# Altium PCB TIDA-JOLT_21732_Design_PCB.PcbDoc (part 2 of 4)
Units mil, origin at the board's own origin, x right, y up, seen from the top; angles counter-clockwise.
Board outline 5511.81 x 3149.61 mil, 4 copper layers (Top Layer, Power, Ground, Bottom Layer), stack 104.204 mil thick; 440 components, 201 nets, 1044 pads, 391 vias.
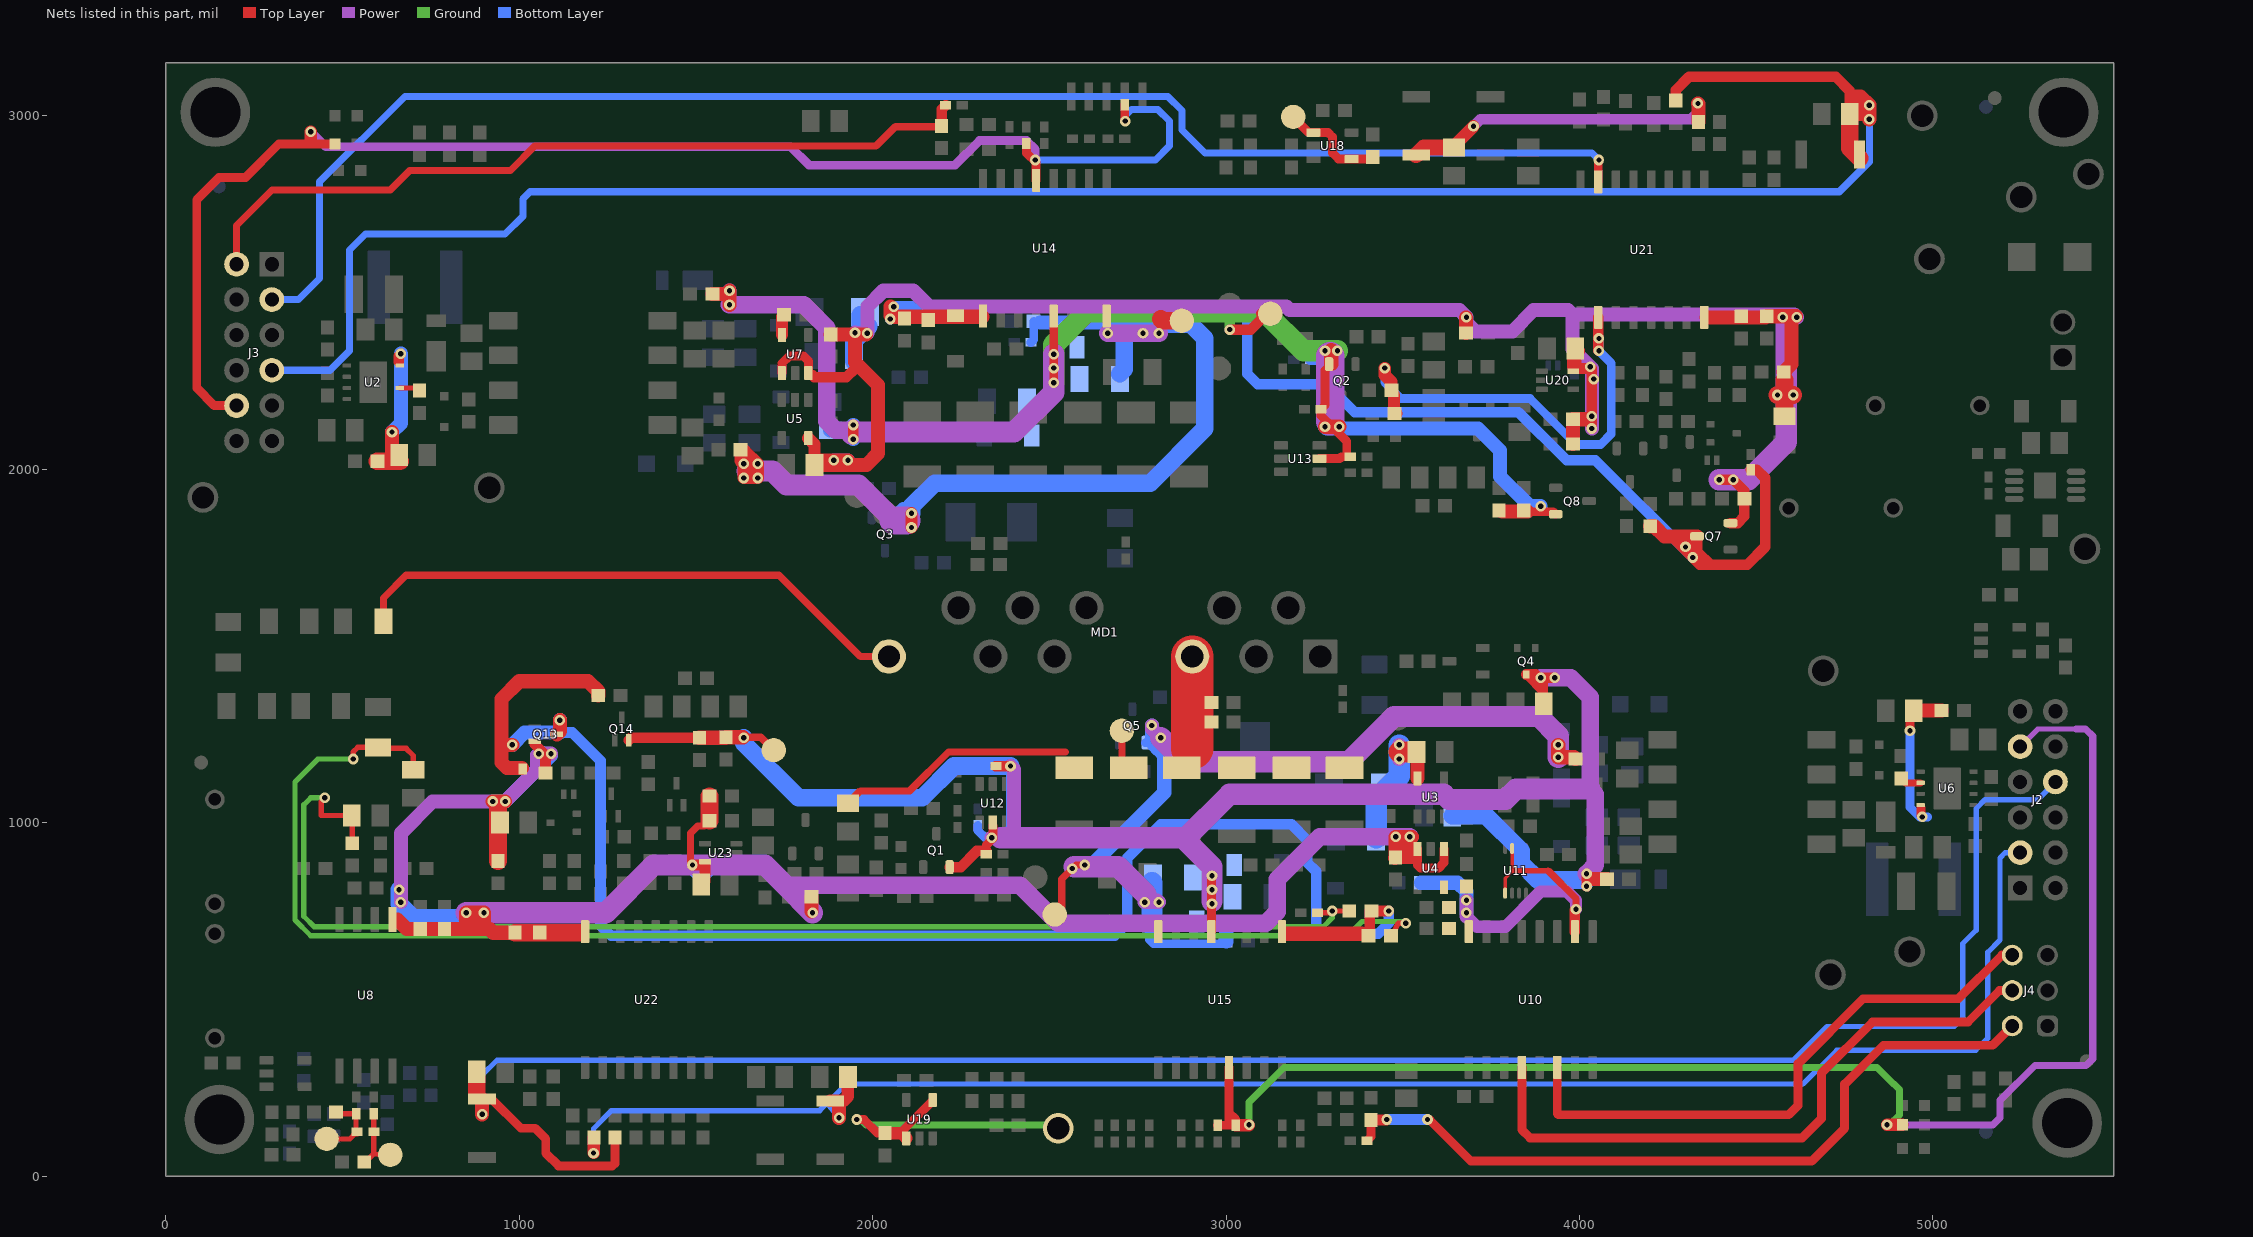
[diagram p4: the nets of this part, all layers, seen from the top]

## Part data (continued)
C3 C25: "CAP, CERM, 0.1 μF, 100 V,+/- 10%, X7R, 0805", Cap_Case=0805, Manufacturer=MuRata, Supplier Part Number 1=490-12005-1-ND, TempCo=X7R, Tolerance_%=10, Value2=100V, ValueDisplayed=0.1μF
C4: library part CMP-0008965-2, "CAP, CERM, 10 uF, 25 V, +/- 10%, X7R, 1206", Cap_Case=2220, Manufacturer=MuRata, Supplier Part Number 1=81-GRM31CR71E106KA12, TempCo=X7R, Tolerance_%=10%, Value1=Unknown, Value2=25V, ValueDisplayed=10uF
C5 C11: library part CMP-0008349-2, "CAP, CERM, 0.1 uF, 50 V, +/- 10%, X7R, 0805", Cap_Case=0805, Manufacturer=MuRata, Supplier Part Number 1=490-1666-1-ND, TempCo=X7R, Tolerance_%=10%, Value1=Unknown, Value2=50V, ValueDisplayed=0.1uF
C6 C26: "CAP, CERM, 220 pF, 100 V,+/- 5%, C0G/NP0, 0603", Cap_Case=0603, Manufacturer=MuRata, Supplier Part Number 1=490-1359-1-ND, TempCo=C0G/NP0, Tolerance_%=5, Value2=100V, ValueDisplayed=220pF
C7 C8 C12 C13 C27 C28 C32 C34: "CAP, CERM, 22 μF, 25 V,+/- 20%, X5R, 0805", Cap_Case=0805, Manufacturer=MuRata, Supplier Part Number 1=490-10749-1-ND, TempCo=X5R, Tolerance_%=20, Value2=25V, ValueDisplayed=22μF
C9 C14 C29 C35: "CAP, CERM, 0.22 μF, 50 V,+/- 10%, X7R, 0805", Cap_Case=0805, Manufacturer=MuRata, Supplier Part Number 1=490-1670-1-ND, TempCo=X7R, Tolerance_%=10, Value2=50V, ValueDisplayed=0.22μF
C10: library part CMP-0008968-2, "CAP, CERM, 2.2 uF, 50 V, +/- 10%, X7R, 1206", Cap_Case=1206, Manufacturer=MuRata, Supplier Part Number 1=490-3367-1-ND, TempCo=X7R, Tolerance_%=10%, Value1=Unknown, Value2=50V, ValueDisplayed=2.2uF
C15 C16 C36 C37: library part CMP-0009609-4, "CAP, CERM, 1500 pF, X1 250 VAC/Y2 300 VAC, +/- 20%, E, TH", Cap_Case=7x5x10mm, Manufacturer=MuRata, Supplier Part Number 1=490-9553-1-ND, TempCo=E, Tolerance_%=20%, Value1=Unknown, ValueDisplayed=1500pF
C17 C38: "CAP, CERM, 0.047 μF, 16 V,+/- 10%, X7R, 0603", Cap_Case=0603, Manufacturer=MuRata, Supplier Part Number 1=490-1529-1-ND, TempCo=X7R, Tolerance_%=10, Value2=16V, ValueDisplayed=0.047μF
C18 C30: library part CMP-0007828-2, "CAP, CERM, 10 uF, 25 V, +/- 10%, X5R, 0805", Cap_Case=0805, Manufacturer=TDK, Supplier Part Number 1=445-5984-1-ND, TempCo=X5R, Tolerance_%=10%, Value1=Unknown, Value2=25V, ValueDisplayed=10uF
C19 C31: library part CMP-0007508-5, "CAP, CERM, 1 uF, 50 V, +/- 10%, X7R, 0603", Cap_Case=0603, Manufacturer="Taiyo Yuden", Supplier Part Number 1=587-3247-1-ND, TempCo=X7R, Tolerance_%=10%, Value1=Unknown, Value2=50V, ValueDisplayed=1uF
C20 C33: library part CMP-0008606-2, "CAP, CERM, 2.2 uF, 16 V, +/- 10%, X7R, 1206", Cap_Case=1206, Manufacturer=Kemet, Supplier Part Number 1=80-C1206C225K4R, TempCo=X7R, Tolerance_%=10%, Value1="0.009 ohm", Value2=16V, ValueDisplayed=2.2uF
C21 C22 C39 C40 C44 C45 C46 C53 C54 C55 C68 C89 C101 C102 C103 C105 C108 C110 C111 C121 C123 C124 C137 C138: "CAP, CERM, 1 μF, 25 V,+/- 10%, X7R, 0603", Cap_Case=0603, Manufacturer=MuRata, Supplier Part Number 1=490-5307-1-ND, TempCo=X7R, Tolerance_%=10, Value2=25V, ValueDisplayed=1μF
C41 C47 C48 C57: "CAP, CERM, 0.01 μF, 50 V,+/- 10%, X7R, 0603", Cap_Case=0603, Manufacturer=MuRata, Supplier Part Number 1=490-1512-1-ND, TempCo=X7R, Tolerance_%=10, Value2=50V, ValueDisplayed=0.01μF
C42 C43 C49 C56 C71 C90 C100 C104 C106 C107 C112 C113 C122 C125 C127: "CAP, CERM, 0.1 μF, 50 V,+/- 10%, X7R, 0603", Cap_Case=0603, Manufacturer=MuRata, Supplier Part Number 1=490-1519-1-ND, TempCo=X7R, Tolerance_%=10, Value2=50V, ValueDisplayed=0.1μF
C50: library part CMP-0006297-2, "CAP, CERM, 0.1 uF, 50 V, +/- 10%, X7R, 0402", Cap_Case=0402, Manufacturer=TDK, PartNumber=C1005X7R1H104K050BB, Supplier Part Number 1=445-5932-1-ND, TempCo=X7R, Tolerance_%=10%, Value1="0.039064 ohm", Value2=50V, ValueDisplayed=0.1uF
C51 C52 C58 C59: "CAP, CERM, 1000 pF, 50 V,+/- 10%, X7R, 0603", Cap_Case=0603, Manufacturer=MuRata, Supplier Part Number 1=490-1494-1-ND, TempCo=X7R, Tolerance_%=10, Value2=50V, ValueDisplayed=1000pF
C60 C61 C62 C63: "CAP, CERM, 100 pF, 100 V,+/- 5%, C0G/NP0, 0603", Cap_Case=0603, Manufacturer=MuRata, Supplier Part Number 1=490-1351-1-ND, TempCo=C0G/NP0, Tolerance_%=5, Value2=100V, ValueDisplayed=100pF
C64 C65: library part CMP-0006562-2, "CAP, CERM, 0.1 uF, 10 V, +/- 10%, X5R, 0402", Cap_Case=0402, Manufacturer=MuRata, PartNumber=GRM155R61A104KA01D, Supplier Part Number 1=490-1318-1-ND, TempCo=X5R, Tolerance_%=10%, Value1=Unknown, Value2=10V, ValueDisplayed=0.1uF
C66 C69 C72 C76: library part CMP-0008584-2, "CAP, CERM, 0.1 uF, 50 V, +/- 5%, X7R, 1206", Cap_Case=1206, Manufacturer=Kemet, Supplier Part Number 1=399-1250-1-ND, TempCo=X7R, Tolerance_%=5%, Value1="0.059 ohm", Value2=50V, ValueDisplayed=0.1uF
C67 C70 C73 C77: library part CMP-0008695-2, "CAP, CERM, 1 uF, 50 V, +/- 10%, X7R, 1206", Cap_Case=1206_180, Manufacturer=TDK, Supplier Part Number 1=445-1423-1-ND, TempCo=X7R, Tolerance_%=10%, Value1="0.009289 ohm", Value2=50V, ValueDisplayed=1uF
C74 C78: library part CMP-0006351-2, "CAP, CERM, 0.1 uF, 16 V, +/- 10%, X7R, 0402", Cap_Case=0402, Manufacturer=MuRata, Supplier Part Number 1=490-4759-2-ND, TempCo=X7R, Tolerance_%=10%, Value1=Unknown, Value2=16V, ValueDisplayed=0.1uF
C75 C79: library part CMP-0006867-4, "CAP, CERM, 1 uF, 25 V, +/- 10%, X7R, 0603", Cap_Case=0603, Manufacturer=Kemet, PartNumber=C0603C105K3RACTU, Supplier Part Number 1=399-7376-1-ND, TempCo=X7R, Tolerance_%=10%, Value1=Unknown, Value2=25V, ValueDisplayed=1uF
C80 C91: library part CMP-0007433-1, "CAP, CERM, 0.01 uF, 50 V, +/- 10%, X7R, 0603", Cap_Case=0603, Manufacturer=MuRata, Supplier Part Number 1=490-1512-1-ND, TempCo=X7R, Tolerance_%=10%, Value1=Unknown, Value2=50V, ValueDisplayed=0.01uF
C81 C82 C83 C84 C85 C92 C93 C94 C95 C96: library part CMP-0006303-2, "CAP, CERM, 100 pF, 50 V, +/- 5%, C0G/NP0, 0402", Cap_Case=0402, Manufacturer="Yageo America", Supplier Part Number 1=311-1024-1-ND, TempCo=C0G/NP0, Tolerance_%=5%, Value1=Unknown, Value2=50V, ValueDisplayed=100pF
C86 C97: library part CMP-0006646-2, "CAP, CERM, 2200 pF, 16 V, +/- 10%, X7R, 0402", Cap_Case=0402, Manufacturer=MuRata, Supplier Part Number 1=GRM155R71C222KA01D-ND, TempCo=X7R, Tolerance_%=10%, Value1=Unknown, Value2=16V, ValueDisplayed=2200pF
C87 C88 C98 C99: library part CMP-0079721-1, "CAP, CERM, 0.01 μF, 25 V,+/- 10%, X7R, 0603", Cap_Case=0603, Manufacturer="Presidio Components", TempCo=X7R, Tolerance_%=10%, Value2=25V, ValueDisplayed=0.01μF
C109 C114 C119 C126 C128 C133: "CAP, CERM, 100 pF, 50 V,+/- 5%, C0G/NP0, 0603", Cap_Case=0603, Manufacturer=MuRata, Supplier Part Number 1=490-1427-1-ND, TempCo=C0G/NP0, Tolerance_%=5, Value2=50V, ValueDisplayed=100pF
C115 C130: "CAP, CERM, 47 pF, 50 V,+/- 5%, C0G/NP0, 0603", Cap_Case=0603, Manufacturer=MuRata, Supplier Part Number 1=490-1419-1-ND, TempCo=C0G/NP0, Tolerance_%=5, Value2=50V, ValueDisplayed=47pF
C116 C129: "CAP, CERM, 0.33 μF, 50 V,+/- 10%, X7R, 0805", Cap_Case=0805, Manufacturer=MuRata, Supplier Part Number 1=490-3327-1-ND, TempCo=X7R, Tolerance_%=10, Value2=50V, ValueDisplayed=0.33μF
C117 C131: "CAP, CERM, 2200 pF, 25 V,+/- 10%, X7R, 0603", Cap_Case=0603, Manufacturer=MuRata, Supplier Part Number 1=GRM188R71E222KA01D-ND, TempCo=X7R, Tolerance_%=10, Value2=25V, ValueDisplayed=2200pF
C118 C120 C132 C134 C135 C136: "CAP, CERM, 470 pF, 50 V,+/- 5%, C0G/NP0, 0603", Cap_Case=0603, Manufacturer=MuRata, Supplier Part Number 1=490-1443-1-ND, TempCo=C0G/NP0, Tolerance_%=5, Value2=50V, ValueDisplayed=470pF
D1: library part CMP-0028407-1, "Diode, Schottky, 60 V, 2 A, SMA", Manufacturer="Diodes Inc.", Supplier Part Number 1=B260A-FDICT-ND, Value1=2A, Value2=0.7V
D2 D11: library part CMP-0005415-2, "Diode, Zener, 24 V, 1 W, PowerDI123", Manufacturer="Diodes Inc.", Power_W=1W, Supplier Part Number 1=DFLZ24DICT-ND
D3 D12: library part CMP-0077072-1, "Diode, Superfast Rectifier, 200 V, 1 A, AEC-Q101, PowerDI123", Manufacturer="Diodes Inc.", Supplier Part Number 1=DFLU1200-7DICT-ND, Value1=1A, Value2=0.98V
D4 D13: library part CMP-0084402-1, "Diode, Zener, 18 V, 500 mW, AEC-Q101, SOD-123", Manufacturer="Diodes Inc.", Power_W=500mW, Value1=0.5W
D5 D14: library part CMP-0029019-1, "Diode, Ultrafast, 75 V, 0.25 A, SOD-323", Manufacturer="Central Semiconductor", Value1=0.25A, Value2=1.2V
D6 D7 D15: library part CMP-0002905-1, "LED, Green, SMD", Color=Green, Manufacturer="Wurth Elektronik", Supplier Part Number 1=732-4971-1-ND, Value1=W, Value2=3.2V
D8 D16: library part CMP-0028782-1, "Diode, Schottky, 100 V, 1 A, AEC-Q101, SOD-123W", Manufacturer=Nexperia, Supplier Part Number 1=568-12693-1-ND, Value1=1A, Value2=0.77V
D9 D18: library part CMP-0005813-1, "Diode, Zener, 8.2 V, 500 mW, SOD-123", Manufacturer="Diodes Inc.", Power_W=500mW, Supplier Part Number 1=BZT52C8V2-FDICT-ND, Value1=0.5W
D10 D17: library part CMP-0005529-3, "Diode, Zener, 5.1 V, 1 W, SMA", Manufacturer="Diodes Inc.", Power_W=1W
D19 D20: "LED, Super Red, SMD", Color="super red", Manufacturer="Wurth Elektronik", Supplier Part Number 1=732-4979-1-ND, Value1=W, Value2=1.9V
D21 D26: library part CMP-0005553-2, "Diode, TVS, Bi, 19 V, SMB", Manufacturer=Littelfuse, Power_W=5W, Supplier Part Number 1=SMBJ20CALFDKR-ND
D22 D23 D24 D27 D28 D29: library part CMP-0002893-1, "LED, Super Red, SMD", Color="super red", Manufacturer="Wurth Elektronik", Supplier Part Number 1=732-4979-1-ND, Value1=W, Value2=1.9V
D25 D30: library part CMP-0077598-3, "Diode, Zener, 4.7 V, 500 mW, SOD-123", Manufacturer=Vishay-Semiconductor, Power_W=500mW, Value1=0.5W
D31 D33 D35 D36 D41 D42: library part CMP-0028877-2, "Diode, Schottky, 30 V, 0.1 A, AEC-Q101, SOD882", Manufacturer=Nexperia, Value1=0.1A, Value2=0.35V
D32 D38: library part CMP-0076957-3, "Diode, Switching, 75 V, 0.3 A, SOD-523", Manufacturer="Micro Commercial Components", Value1=0.3A, Value2=1.25V
FID1 FID2 FID3 FID4 FID5 FID6: library part CMP-0077181-1, "Fiducial mark.  There is nothing to buy or mount.", Manufacturer=N/A
"High Voltage" High_Voltage: library part IEC_HighVoltage, "IEC 61010-1 High Voltage Warning"
J1: library part CMP-0075076-1, "Terminal Block, 2.54mm, 2x1, Brass, TH", Manufacturer="On-Shore Technology", Supplier Part Number 1=ED10561-ND
J2 J3: library part CMP-0075545-2, "Header, 2.54 mm, 6x2, Gold, R/A,TH", Color=Black, Current_A=6.3A, Manufacturer=Samtec, Supplier Part Number 1=SAM1049-06-ND, Voltage_V=550V
J4: library part CMP-0077741-2, "Header, 2.54mm, 3x2, Gold, R/A, TH", Color=Black, Current_A=3A, Manufacturer=Molex, Supplier Part Number 1=WM50030-06-ND, Voltage_V=350V
Logo1: library part CMP-0074839-1
Logo2: library part CMP-0074847-1, "FCC_disclaimer"
MD1: library part CMP-0086469-1, "MOD IGBT MED PWR 14MDIP", Manufacturer="Infineon Technologies"
Q1 Q2: library part "BC857C-7-F, Diodes Inc.", "Transistor, PNP, 45 V, 0.1 A, SOT-23", Manufacturer="Diodes Inc.", Supplier Part Number 1=BC857C-FDICT-ND, Value1="0.1 A", Value2=600
Q3 Q5 Q9 Q17: library part CMP-0000739-1, "MOSFET, N-CH, 40 V, 5.6 A, SOT-23", Alternate Manufacturer=None, Manufacturer=Vishay-Siliconix, Supplier Part Number 1=SI2318CDS-T1-GE3CT-ND, Value1=0.05, Value2="5.8 nC"
Q4: library part CMP-0000406-2, "Transistor, NPN, 40 V, 0.2 A, SOT-323", Manufacturer="Diodes Inc.", Supplier Part Number 1=MMST3904-FDICT-ND, Value1="0.2 A", Value2=400
Q6 Q12: library part CMP-0000759-1, "MOSFET, N-CH, 50 V, 0.3 A, SOT-323", Alternate Manufacturer=None, Manufacturer="Diodes Inc.", Supplier Part Number 1=DMN5L06WKDICT-ND
Q7 Q8: library part CMP-0064870-1, "Transistor, PNP, 60 V, 1 A, AEC-Q101, SOT-23", Manufacturer="Diodes Inc.", Supplier Part Number 1=DPBT8105DICT-ND, Value1="1 A", Value2=300
Q10 Q11: library part CMP-0064871-1, "Transistor, NPN, 60 V, 1 A, AEC-Q101, SOT-23", Manufacturer="Diodes Inc.", Supplier Part Number 1=DNBT8105DICT-ND, Value1="1 A", Value2=300
Q13 Q14: library part CMP-0000362-2, "Transistor, PNP, 60 V, 0.6 A, AEC-Q101, SOT-523", Manufacturer="Diodes Inc.", Supplier Part Number 1=MMBT2907AT-FDICT-ND, Value1="0.6 A", Value2=300
Q15 Q16: library part CMP-0000405-2, "Transistor, NPN, 40 V, 0.2 A, SOT-523", Manufacturer="Diodes Inc.", Supplier Part Number 1=MMBT3904T-FDICT-ND, Value1="0.2 A", Value2=300
R1 R12: "RES, 100, 1%, 0.125 W, 0805", Manufacturer=Vishay-Dale, Power_W=0.125, Supplier Part Number 1=541-100CCT-ND, TempCo="100 ppm/C", Tolerance_%=1, Value1=1%, Value2=0.125W, Value_Code=100R, ValueDisplayed=100
R2 R8 R13 R19 R108 R109: library part CMP-0025874-3, "RES, 0, 5%, 0.1 W, 0603", Manufacturer=Panasonic, Power_W=100mW, Supplier Part Number 1=P0.0GCT-ND, TempCo="600 ppm/C", Tolerance_%=5%, Value2=0.1W, Value_Code=0000, ValueDisplayed=0
R3 R14: "RES, 20.0 k, 1%, 0.125 W, 0805", Manufacturer=Vishay-Dale, Power_W=0.125, Supplier Part Number 1=541-20.0KCCT-ND, TempCo="100 ppm/C", Tolerance_%=1, Value1=1%, Value2=0.125W, Value_Code=20k0, ValueDisplayed=20.0k
R4: "RES, 3.32 k, 1%, 0.063 W, 0402", Manufacturer=Vishay-Dale, Power_W=0.063, Supplier Part Number 1=541-3.32KLCT-ND, TempCo="100 ppm/C", Tolerance_%=1, Value1=1%, Value2=0.063W, Value_Code=3k32, ValueDisplayed=3.32k
R5 R16: "RES, 100 k, 1%, 0.125 W, 0805", Manufacturer=Vishay-Dale, Power_W=0.125, Supplier Part Number 1=541-100KCCT-ND, TempCo="100 ppm/C", Tolerance_%=1, Value1=1%, Value2=0.125W, Value_Code=100k
R6 R17: "RES, 154 k, 1%, 0.1 W, 0603", Manufacturer=Vishay-Dale, Power_W=0.1, Supplier Part Number 1=541-154KHCT-ND, TempCo="100 ppm/C", Tolerance_%=1, Value1=1%, Value2=0.1W, Value_Code=154k
R7 R18: "RES, 301 k, 1%, 0.1 W, 0603", Manufacturer=Vishay-Dale, Power_W=0.1, Supplier Part Number 1=541-301KHCT-ND, TempCo="100 ppm/C", Tolerance_%=1, Value1=1%, Value2=0.1W, Value_Code=301k
R9 R20: "RES, 976 k, 1%, 0.1 W, 0603", Manufacturer=Vishay-Dale, Power_W=0.1, Supplier Part Number 1=541-976KHCT-ND, TempCo="100 ppm/C", Tolerance_%=1, Value1=1%, Value2=0.1W, Value_Code=976k
R10 R15: library part CMP-0020448-2, "RES, 10, 5%, 0.125 W, 0805", Manufacturer=Vishay-Dale, Power_W=125mW, Supplier Part Number 1=541-10ACT-ND, TempCo="200 ppm/C", Tolerance_%=5%, Value2=0.125W, Value_Code=10R0, ValueDisplayed=10
R11 R21: "RES, 12.1 k, 1%, 0.125 W, 0805", Manufacturer=Vishay-Dale, Power_W=0.125, Supplier Part Number 1=541-12.1KCCT-ND, TempCo="100 ppm/C", Tolerance_%=1, Value1=1%, Value2=0.125W, Value_Code=12k1, ValueDisplayed=12.1k
R22 R23 R24 R25 R26 R27: "RES, 221 k, 1%, 0.25 W, 1206", Manufacturer=Vishay-Dale, Power_W=0.25, Supplier Part Number 1=541-221KFCT-ND, TempCo="100 ppm/C", Tolerance_%=1, Value1=1%, Value2=0.25W, Value_Code=221k
R28 R31 R118 R119 R120 R126 R143 R144 R145 R151: "RES, 2.49 k, 1%, 0.125 W, 0805", Manufacturer=Vishay-Dale, Power_W=0.125, Supplier Part Number 1=541-2.49KCCT-ND, TempCo="100 ppm/C", Tolerance_%=1, Value1=1%, Value2=0.125W, Value_Code=2k49, ValueDisplayed=2.49k
R29 R71 R79 R99 R105: "RES, 0, 5%, 0.1 W, 0603", Manufacturer=Vishay-Dale, Power_W=0.1, Supplier Part Number 1=541-0.0GCT-ND, TempCo="200 ppm/C", Tolerance_%=5, Value1=5%, Value2=0.1W, Value_Code=0000, ValueDisplayed=0
R30 R40 R131 R161: "RES, 15.0 k, 1%, 0.1 W, 0603", Manufacturer=Vishay-Dale, Power_W=0.1, Supplier Part Number 1=541-15.0KHCT-ND, TempCo="100 ppm/C", Tolerance_%=1, Value1=1%, Value2=0.1W, Value_Code=15k0, ValueDisplayed=15.0k
R32 R33 R37 R38: "RES, 4.64 k, 1%, 0.1 W, 0603", Manufacturer=Vishay-Dale, Power_W=0.1, Supplier Part Number 1=541-4.64KHCT-ND, TempCo="100 ppm/C", Tolerance_%=1, Value1=1%, Value2=0.1W, Value_Code=4k64, ValueDisplayed=4.64k
R34 R35: "RES, 1.21 k, 1%, 0.1 W, 0603", Manufacturer=Vishay-Dale, Power_W=0.1, Supplier Part Number 1=541-1.21KHCT-ND, TempCo="100 ppm/C", Tolerance_%=1, Value1=1%, Value2=0.1W, Value_Code=1k21, ValueDisplayed=1.21k
R36 R72 R101: "RES, 49.9, 1%, 0.1 W, 0603", Manufacturer=Vishay-Dale, Power_W=0.1, Supplier Part Number 1=541-49.9HCT-ND, TempCo="100 ppm/C", Tolerance_%=1, Value1=1%, Value2=0.1W, Value_Code=49R9, ValueDisplayed=49.9
R39 R42: library part CMP-0025963-2, "RES, 10.0, 1%, 0.063 W, 0402", Manufacturer=Vishay-Dale, Power_W=63mW, Supplier Part Number 1=541-10.0LCT-ND, TempCo="100 ppm/C", Tolerance_%=1%, Value2=0.063W, Value_Code=10R0, ValueDisplayed=10.0
R41 R78 R82: library part CMP-0026822-3, "RES, 0, 5%, 0.063 W, AEC-Q200 Grade 0, 0402", Manufacturer=Vishay-Dale, Power_W=63mW, Supplier Part Number 1=541-0.0JCT-ND, TempCo="200 ppm/C", Tolerance_%=5%, Value2=0.063W, Value_Code=0000, ValueDisplayed=0
R43 R44 R130 R154: "RES, 2.49 k, 1%, 0.1 W, 0603", Manufacturer=Vishay-Dale, Power_W=0.1, Supplier Part Number 1=541-2.49KHCT-ND, TempCo="100 ppm/C", Tolerance_%=1, Value1=1%, Value2=0.1W, Value_Code=2k49, ValueDisplayed=2.49k
R45 R46: library part CMP-0026403-1, "RES, 49.9 k, 1%, 0.063 W, 0402", Manufacturer=Vishay-Dale, Power_W=63mW, Supplier Part Number 1=541-49.9KLCT-ND, TempCo="100 ppm/C", Tolerance_%=1%, Value2=0.063W, Value_Code=49k9, ValueDisplayed=49.9k
R47 R49: "RES, 240 k, 1%, 0.063 W, 0402", Manufacturer=Vishay-Dale, Power_W=0.063, Supplier Part Number 1=541-240KLCT-ND, TempCo="100 ppm/C", Tolerance_%=1, Value1=1%, Value2=0.063W, Value_Code=240k
R48 R50: "RES, 10.0 k, 1%, 0.063 W, 0402", Manufacturer=Vishay-Dale, Power_W=0.063, Supplier Part Number 1=541-10.0KLCT-ND, TempCo="100 ppm/C", Tolerance_%=1, Value1=1%, Value2=0.063W, Value_Code=10k0, ValueDisplayed=10.0k
R51 R54: "RES, 1.82 k, 1%, 0.063 W, 0402", Manufacturer=Vishay-Dale, Power_W=0.063, Supplier Part Number 1=541-1.82KLCT-ND, TempCo="100 ppm/C", Tolerance_%=1, Value1=1%, Value2=0.063W, Value_Code=1k82, ValueDisplayed=1.82k
R52 R53: "RES, 11.0 k, 1%, 0.1 W, 0603", Manufacturer=Vishay-Dale, Power_W=0.1, Supplier Part Number 1=541-11.0KHCT-ND, TempCo="100 ppm/C", Tolerance_%=1, Value1=1%, Value2=0.1W, Value_Code=11k0, ValueDisplayed=11.0k
R55 R170: "RES, 3.32 k, 1%, 0.1 W, 0603", Manufacturer=Vishay-Dale, Power_W=0.1, Supplier Part Number 1=541-3.32KHCT-ND, TempCo="100 ppm/C", Tolerance_%=1, Value1=1%, Value2=0.1W, Value_Code=3k32, ValueDisplayed=3.32k
R56 R57: "RES, 5.76 k, 1%, 0.063 W, 0402", Manufacturer=Vishay-Dale, Power_W=0.063, Supplier Part Number 1=541-5.76KLCT-ND, TempCo="100 ppm/C", Tolerance_%=1, Value1=1%, Value2=0.063W, Value_Code=5k76, ValueDisplayed=5.76k
R58 R83: "RES, 10, 5%, 0.125 W, 0805", Manufacturer=Vishay-Dale, Power_W=0.125, Supplier Part Number 1=541-10ACT-ND, TempCo="200 ppm/C", Tolerance_%=5, Value1=5%, Value2=0.125W, Value_Code=10R0, ValueDisplayed=10
R59 R60 R61 R85 R86 R87: library part CMP-0026754-1, "RES, 10.0 k, 1%, 0.063 W, AEC-Q200 Grade 0, 0402", Manufacturer="Stackpole Electronics Inc", Power_W=63mW, Supplier Part Number 1=RMCF0402FT10K0CT-ND, TempCo="100 ppm/C", Tolerance_%=1%, Value2=0.063W, Value_Code=10k0, ValueDisplayed=10.0k
R62 R64 R88 R90: library part CMP-0025951-2, "RES, 100, 1%, 0.063 W, 0402", Manufacturer=Vishay-Dale, PartNumber=CRCW0402100RFKED, Power_W=63mW, Supplier Part Number 1=541-100LCT-ND, TempCo="100 ppm/C", Tolerance_%=1%, Value2=0.063W, Value_Code=100R, ValueDisplayed=100
R63 R65 R66 R67 R68 R70 R89 R91 R93 R94 R95 R98: "RES, 5.1, 5%, 0.75 W, AEC-Q200 Grade 0, 2010", Manufacturer=Vishay-Dale, Power_W=0.75, Supplier Part Number 1=541-5.1WCT-ND, TempCo="200 ppm/C", Tolerance_%=5, Value1=5%, Value2=0.75W, Value_Code=5R10, ValueDisplayed=5.1
R69 R96 R121 R147: "RES, 10.0 k, 1%, 0.1 W, 0603", Manufacturer=Vishay-Dale, Power_W=0.1, Supplier Part Number 1=541-10.0KHCT-ND, TempCo="100 ppm/C", Tolerance_%=1, Value1=1%, Value2=0.1W, Value_Code=10k0, ValueDisplayed=10.0k
R73 R100: "RES, 10.0, 0.1%, 0.1 W, 0603", Manufacturer=Vishay-Dale, Power_W=0.1, Supplier Part Number 1=TNP10.0AACT-ND, TempCo="25 ppm/C", Value1=0.1%, Value2=0.1W, Value_Code=10R0, ValueDisplayed=10.0
R74 R80 R84 R106: "RES, 2.00, 1%, 0.25 W, 1206", Manufacturer=Vishay-Dale, Power_W=0.25, Supplier Part Number 1=541-2.00FFCT-ND, TempCo="100 ppm/C", Tolerance_%=1, Value1=1%, Value2=0.25W, Value_Code=2R00, ValueDisplayed=2.00
R75 R76 R77 R102 R103 R104: "RES, 3.48 k, 1%, 0.1 W, 0603", Manufacturer=Vishay-Dale, Power_W=0.1, Supplier Part Number 1=541-3.48KHCT-ND, TempCo="100 ppm/C", Tolerance_%=1, Value1=1%, Value2=0.1W, Value_Code=3k48, ValueDisplayed=3.48k
R81 R107 R111 R113 R114 R116 R134 R135 R137 R138 R139 R142 R157 R158 R160 R163 R164 R166: "RES, 10.2 k, 1%, 0.1 W, 0603", Manufacturer=Vishay-Dale, Power_W=0.1, Supplier Part Number 1=541-10.2KHCT-ND, TempCo="100 ppm/C", Tolerance_%=1, Value1=1%, Value2=0.1W, Value_Code=10k2, ValueDisplayed=10.2k
R92 R122 R148: "RES, 10.0 k, 1%, 0.125 W, 0805", Manufacturer=Vishay-Dale, Power_W=0.125, Supplier Part Number 1=541-10.0KCCT-ND, TempCo="100 ppm/C", Tolerance_%=1, Value1=1%, Value2=0.125W, Value_Code=10k0, ValueDisplayed=10.0k
R97: "RES, 2.49 k, 0.1%, 0.125 W, 0805", Manufacturer="Yageo America", Power_W=0.125, Supplier Part Number 1=9982892, TempCo="25 ppm/C", Tolerance_%=0.1, Value1=0.1%, Value2=0.125W, Value_Code=2k49, ValueDisplayed=2.49k
R110 R112 R129 R153: "RES, 1.02 k, 1%, 0.1 W, 0603", Manufacturer=Vishay-Dale, Power_W=0.1, Supplier Part Number 1=541-1.02KHCT-ND, TempCo="100 ppm/C", Tolerance_%=1, Value1=1%, Value2=0.1W, Value_Code=1k02, ValueDisplayed=1.02k
R115 R117: "RES, 100 k, 1%, 0.1 W, 0603", Manufacturer=Vishay-Dale, Power_W=0.1, Supplier Part Number 1=541-100KHCT-ND, TempCo="100 ppm/C", Tolerance_%=1, Value1=1%, Value2=0.1W, Value_Code=100k
R123 R150: "RES, 4.02 k, 1%, 0.125 W, 0805", Manufacturer=Vishay-Dale, Power_W=0.125, Supplier Part Number 1=541-4.02KCCT-ND, TempCo="100 ppm/C", Tolerance_%=1, Value1=1%, Value2=0.125W, Value_Code=4k02, ValueDisplayed=4.02k
R124 R146: "RES, 470, 5%, 0.1 W, 0603", Manufacturer=Vishay-Dale, Power_W=0.1, Supplier Part Number 1=541-470GCT-ND, TempCo="200 ppm/C", Tolerance_%=5, Value1=5%, Value2=0.1W, Value_Code=470R, ValueDisplayed=470
R125 R127 R141 R149 R152 R167: "RES, 4.99 k, 1%, 0.1 W, 0603", Manufacturer=Vishay-Dale, Power_W=0.1, Supplier Part Number 1=541-4.99KHCT-ND, TempCo="100 ppm/C", Tolerance_%=1, Value1=1%, Value2=0.1W, Value_Code=4k99, ValueDisplayed=4.99k
R128 R132 R155 R162: "RES, 3.01 k, 1%, 0.125 W, 0805", Manufacturer=Vishay-Dale, Power_W=0.125, Supplier Part Number 1=541-3.01KCCT-ND, TempCo="100 ppm/C", Tolerance_%=1, Value1=1%, Value2=0.125W, Value_Code=3k01, ValueDisplayed=3.01k
R133 R136 R156 R159 R168 R169: "RES, 100, 1%, 0.1 W, 0603", Manufacturer=Vishay-Dale, Power_W=0.1, Supplier Part Number 1=541-100HCT-ND, TempCo="100 ppm/C", Tolerance_%=1, Value1=1%, Value2=0.1W, Value_Code=100R, ValueDisplayed=100
R140 R165: "RES, 24.9, 1%, 0.125 W, 0805", Manufacturer=Vishay-Dale, Power_W=0.125, Supplier Part Number 1=541-24.9CCT-ND, TempCo="100 ppm/C", Tolerance_%=1, Value1=1%, Value2=0.125W, Value_Code=24R9, ValueDisplayed=24.9
R171: "RES, 9.09 k, 1%, 0.1 W, 0603", Manufacturer=Vishay-Dale, Power_W=0.1, Supplier Part Number 1=541-9.09KHCT-ND, TempCo="100 ppm/C", Tolerance_%=1, Value1=1%, Value2=0.1W, Value_Code=9k09, ValueDisplayed=9.09k
S1 S2 S3 S4 S5 S6: library part CMP-0002113-2, "Switch, Push Button, SMD", CurrentRating_mA=50A, Manufacturer=Alps, Supplier Part Number 1=688-SKRKAE
T1 T?: library part CMP-0087757-1, "Flyback Transformer", Manufacturer=Coilcraft
TP1 TP3 TP18 TP26: library part CMP-0055142-1, "Test Point, Compact, Red, TH", Color=Red, Manufacturer=Keystone, Supplier Part Number 1=36-5005-ND
TP2 TP23 TP24: library part CMP-0055143-1, "Test Point, Compact, Black, TH", Color=Black, Manufacturer=Keystone, Supplier Part Number 1=36-5006-ND
TP4 TP5 TP6 TP7 TP8 TP9 TP10 TP11 TP12 TP17 TP19 TP20 TP21 TP22 TP25: library part CMP-0055027-1, "PCB Pin, 20mil Dia, Gold, TH", Manufacturer=Mill-Max, Supplier Part Number 1=ED90418-ND
TP13 TP14 TP15 TP16: library part CMP-0055155-1, "Test Point, Compact, Blue, TH", Color=Blue, Manufacturer=Keystone, Supplier Part Number 1=36-5122-ND
U1: library part CMP-0013313-4, "300mA High-Voltage Ultra-Low-Iq Low-Dropout (LDO) Regulator, DGN0008D (VSSOP-8)", Alternate Manufacturer="Texas Instruments"
U2 U6: library part CMP-0078633-2, "70-V PSR Flyback Converter With 100-V, 1.2-A Power Switch and Ultra-Low IQ, NGU0008C (WSON-8)", Alternate Manufacturer="Texas Instruments", Alternate PartNumber=LM5180QNGUTQ1
U3 U5: library part CMP-0079136-1, "150-mA, 30-V, Ultra-Low IQ, Wide Input LDO with Reverse Current Protection for Automotive, DBV0005A (SOT-23-5)", Alternate Manufacturer="Texas Instruments"
U4 U7: library part CMP-0073750-1, "Capacitor-Free, 150-mA, LDO Regulator w/ Foldback Current Limit, DBV0005A (SOT-23-5)", Alternate Manufacturer="Texas Instruments"
U8: library part CMP-0013503-2, "Precision, 2-V Input, Reinforced Isolated Amplifier, DWV0008A (SOIC-8)", Alternate Manufacturer="Texas Instruments", Alternate PartNumber=AMC1311DWV, PartNumber=AMC1311QDWVRQ1
U9: library part CMP-0077859-1, "Automotive Qualified Precision, Zero-Crossover, 20MHz, 0.9pA Ib, RRIO, CMOS Operational Amplifier, DBV0005A (SOT-23-5)", Alternate Manufacturer="Texas Instruments", Alternate PartNumber=OPA320AQDBVTQ1
U10: library part CMP-0076066-3, "Automotive, High Speed, Robust EMC Quad-Channel Digital Isolators, DW0016B (SOIC-16)", Alternate Manufacturer="Texas Instruments", Alternate PartNumber=ISO7742FQDWQ1, Operating Temperature Range="-40 to 125 C", Rating=Automotive
U11: library part CMP-0075945-2, "Ultra-Low-Power Ultra-Small-Size 12-Bit 2MSPS SAR ADC, DCU0008A (VSSOP-8)", Alternate Manufacturer="Texas Instruments", Operating Temperature Range="-40 to 125 C", Rating=Automotive
U12 U13: library part CMP-0067337-2, "Automotive, High-Voltage (18V) Window Comparator with Over- and Undervoltage Detection, DDC0006A (SOT-23-T-6)", Alternate Manufacturer="Texas Instruments"
U14 U15: library part CMP-0080538-2, "Single Channel Isolated Gate Driver for SiC/IGBT with Advanced Protection and High-CMTI, DW0016B (SOIC-16)", Alternate Manufacturer="Texas Instruments", Alternate PartNumber=UCC21732QDWRQ1
U16: library part CMP-0033164-1, "Automotive Catalog Adjustable Precision Shunt Regulator, 34 ppm / degC, 100 mA, -40 to 125 degC, 3-pin SOT-23 (DBZ), Green (RoHS & no Sb/Br)", Manufacturer="Texas Instruments", Rating=Automotive, Temp Coeff(Typ)(ppm/ degree C)=34
U17: library part CMP-0051573-1, "Automotive Catalog Single 2-Input Positive-AND Gate, DBV0005A, LARGE T&R", F @ Nom Voltage(Max)(Mhz)=75, Generic Part Number=SN74AHC1G08-Q1, ICC @ Nom Voltage(Max)(mA)=0.01, Manufacturer="Texas Instruments", Operating Temperature Range(C)="-40 to 125", Rating=Automotive, tpd @ Nom Voltage(Max)(ns)=12.3,7.9, Voltage(Nom)(V)=3.3,5
U18 U19: library part CMP-0042686-1, "Automotive Catalog 550 uA/Ch, 3 MHz, Rail-to-Rail Output Operational Amplifier, 2.7 to 16 V, -40 to 125 degC, 5-pin SOT23 (DBV5), Green (RoHS & no Sb/Br)", Manufacturer="Texas Instruments", Rating=Automotive, Total Supply Voltage(Max)(+5V is 5, +/-5V is 10)=16, Total Supply Voltage(Min)(+5V is 5, +/-5V is 10)=2.7
U20 U23: library part CMP-0073518-3, "40ns, micro-Power, Rail-to-Rail Input, Single-Channel Comparator with Push-Pull Outputs, DCK0005A (SOT-SC70-5)", Alternate Manufacturer="Texas Instruments", Alternate PartNumber=TLV3201AIDCKT
U21 U22: library part CMP-0860136-1, "Automotive, High Speed, Robust EMC Six-Channel Digital Isolators, DW0016B (SOIC-16)", Alternate Manufacturer="Texas Instruments", Alternate PartNumber=ISO7762FQDWRQ1, Operating Temperature Range="-40 to 125 C", Rating=Automotive
ZZ1: library part CMP-0003616-3
ZZ2: library part CMP-0077236-1
ZZ3: library part CMP-0077237-1
ZZ4: library part CMP-0077238-1

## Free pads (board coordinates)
  round 196.85 hole 141.73: 1(140,3010) 1(151.46,160) 1(5370,3010) 1(5380,150)

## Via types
v1: diameter 30, hole 15, Top Layer to Bottom Layer, 378 vias
v2: diameter 19.68, hole 7.87, Top Layer to Bottom Layer, 13 vias

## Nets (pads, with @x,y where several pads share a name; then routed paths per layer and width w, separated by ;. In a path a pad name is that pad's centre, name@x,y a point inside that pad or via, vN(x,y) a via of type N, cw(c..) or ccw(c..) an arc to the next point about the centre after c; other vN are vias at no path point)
0VInj_AIN_L: J2.3 R151.1 R169.1 S6.2 | length 4951.1
  Top Layer w35: v1@1211.17,66.17 R169.1@1211.17,108.5 ; S6.2@1880,212.68 1917.68,212.68 1930,225 R151.1@1930,280
  Top Layer w40: v1(1905,165) S6.2@1905,210
  Bottom Layer w15: v1(1210,65) 1210,133.83 1261.17,185 1850,185 1925.2,260.2 4632.2,260.2 4727.95,355.95 5120.95,355.95 5155,390 5155,633 5189.8,667.8 5189.8,900 5204.76,914.96 J2.3@5246.77,914.96 ; 1875,200 v1(1905,165)
0VInj_AIN_U: R126.1 R168.1 S3.2 | length 928.2
  Top Layer w35: R126.1@3645,2910 3645,2915 v1(3700,2970)
  Top Layer w40: v1(4335,3035) 4336.75,3033.25 R168.1@4336.75,2982.8
  Top Layer w45: S3.2@3537.91,2888.62 3559.29,2910 R126.1@3645,2910
  Power w30: v1(3700,2970) 3720,2990 4315,2990 4335,3010 v1(4335,3035)
5VInj_AIN_L: J2.8 R145.1 R156.1 S5.2 | length 5891.8
  Top Layer w25: S5.2@895,217.68 922.32,217.68 1005,135 1045,135 1075,105 1075,65 1111.42,28.58 1188.77,28.58 1189.06,28.29 1263.29,28.29 1270.87,35.87 R156.1@1270.87,108.5
  Top Layer w40: v1(895,175) S5.2@895,217.68
  Top Layer w50: S5.2@880,230 R145.1@880,295
  Bottom Layer w15: v1(895,175) 895,285.59 936.96,327.55 4604.3,327.55 4700.05,423.31 5060,423.31 5084.3,447.6 5084.3,657.55 5122.45,695.7 5122.45,1040 5147.45,1065 5296.81,1065 J2.8@5346.77,1114.96
5VInj_AIN_U: J3.7 R120.1 R133.1 S2.2 | length 6023.2
  Top Layer w30: R133.1@4272.04,3042.8 4272.04,3072.04 4310,3110 4725,3110 4765,3070 R120.1@4765,3005
  Top Layer w40: 4795,3005 4795,3040 4780,3055 4795,3055 v1(4820,3030) v1(4820,2990)
  Top Layer w50: R120.1@4765,3005 4765,2907.68 S2.2@4792.68,2880
  Bottom Layer w20: J3.7@300,2280 465,2280 520,2335 520,2620 565,2665 960,2665 1010,2715 1010,2765 1030,2785 4735,2785 4820,2870 v1(4820,2990) v1(4820,3030)
15V_Fault_U: R53.2 R170.2 U21.10 | length 1271.7
  Top Layer w25: v1@4052.91,2337.09 v1(4055,2335)
  Top Layer w30: v1@4052.91,2337.09 U21.10@4052.91,2429.37
  Top Layer w35: v1(3448.7,2286.09) 3448.7,2266.31 3468.03,2246.98 R53.2@3468.03,2223.59 ; R53.2@3475,2210 3475,2164.25 R170.2@3481.5,2157.76
  Bottom Layer w25: v1(3448.7,2286.09) 3448.7,2246.3 3495,2200 3860,2200 3990,2070 4060,2070 4090,2100 4090,2300 v1(4055,2335) v1(4055,2370)
15V_Monitor_L: J4.6 U10.6 | length 1675.4
  Top Layer w25: U10.6@3937.05,307.44 3937.05,176.57 3940,173.62 4592.13,173.62 4618.5,200 4618.5,317.98 4802.02,501.5 5072.02,501.5 5195.49,624.96 J4.6@5224.33,624.96
15V_Monitor_U: J3.3 U21.7 | length 4322.8
  Top Layer w25: U21.7@4052.91,2813.23 4052.91,2872.91 v1(4055,2875)
  Bottom Layer w20: J3.3@300,2480 375,2480 435,2540 435,2813.5 676.5,3055 2835,3055 2875,3015 2875,2960 2940,2895 4035,2895 v1(4055,2875)
+3.3V_L: C22.1 C53.2 C54.1 C56.2 U4.5 U10.10 U10.16 U11.1 U11.7 | length 1076.7
  Top Layer w10: U11.1@3789.45,800.63 3789.45,843.07 3809.13,862.76 U11.7@3809.13,926.61
  Top Layer w15: 3814.13,862.76 3815,863.62 3911.38,863.62
  Top Layer w20: 3911.38,863.62 3990,785 v1(3990,755)
  Top Layer w30: U10.10@3987.05,691.3 v1@3987.05,752.05
  Power w35: v1@3680,735 3710,705 3790,705 3890,805 3965,805 3990,780 v1(3990,755)
  Power w40: v1@3680,735 v1(3680,745) v1(3680,780)
  Bottom Layer w40: C54.1@3551.5,830 3655,830 3680,805 v1(3680,780) v1(3680,745)
+3.3V_U: C40.1 U7.5 | length 59.6
  Top Layer w25: C40.1@1743.3,2431.23 C40.1@1749.2,2437.14
  Top Layer w35: U7.5@1743.3,2380.01 C40.1@1743.3,2431.23
+5V_L: C18.2 C20.1 C21.1 C42.1 C45.2 C122.2 C123.1 C124.2 C126.1 C127.2 D10.1 D41.1 Q13.2 R144.2 R147.2 R149.2 R150.2 U3.5 U4.1 U4.3 U8.1 U22.16 U23.5 | length 6707.6
  Top Layer w20: v1(1490,880) 1485,885 1485,970 1505,990 1523.5,990 C126.1@1538.5,1005
  Top Layer w25: C21.1@3477.48,900 3482.48,895 3541.57,895 ; U4.3@3541.57,925.39 3541.57,895 ; U4.1@3616.38,925.39 3616.38,886.38 3601.26,871.26 3550,871.26 3541.57,879.68 3541.57,895
  Top Layer w30: 1043.5,1221.5 1074.17,1190.83 R149.2@1074.17,1140 ; v1(1490,880) 1516.3,880 ; R150.2@1525.71,834.29 1525.71,880
  Top Layer w40: 655,725 681.5,698.5 C45.2@720.04,698.5 C42.1@788.74,698.5 850,698.5 ; 883.5,720 850,720 ; 900,703.5 v1(900,745) v1(850,745) 850,720 ; v1(925,1060) v1(960,1060) ; C124.2@988.11,688.5 926.5,688.5 916.5,698.5 850,698.5 ; v1@1826.5,748.5 R147.2@1826.5,790 ; C21.1@3477.48,900 C21.1@3478.98,901.5 ; v1@3526.46,958.98 3478.98,958.98 C21.1@3478.98,901.5 ; U4.3@3530,925.39 3502.87,925.39 C21.1@3478.98,901.5 ; C18.2@3538.98,1200 3541.57,1197.4 U3.5@3541.57,1125.39 ; 850,698.5 850,720
  Top Layer w50: C123.1@940,891.5 R144.2@940,994.33 ; 940,1045 R144.2@940,994.33 ; R144.2@945.67,1000 R144.2@940,994.33 ; C124.2@988.11,688.5 C127.2@1058.11,688.5 1172,688.5 ; C126.1@1538.5,1005 C122.2@1538.5,1075
  Top Layer w60: 3490,1200 C18.2@3530,1200
  Power w40: v1(665,775) 665,970 755,1060 v1(925,1060) v1(960,1060) 1050,1150 1050,1190 v1(1055,1195) v1(1090,1195) ; v1(3490,1180) v1(3490,1220)
  Power w50: 1751.77,823.23 2416.77,823.23 2525,715 3112.64,715 3145,747.36 3145,840 3265,960 v1(3480,960) v1(3520,960)
  Power w60: v1(850,745) v1(900,745) 1245,745 1380,880 v1(1490,880) 1695,880 1751.77,823.23 v1(1830,745)
  Bottom Layer w30: v1(1490,880) 1490,865 1496.97,858.03 D41.1@1535,858.03
  Bottom Layer w40: v1(925,1060) v1(960,1060) 1090,1190 1085,1195 v1(1055,1195) 1050,1190 1050,1155.35 ; C20.1@3430,951.91 C20.1@3424.65,957.27 v1@3477.27,957.27
  Bottom Layer w50: v1(660,810) 660,770 700,730 835,730 v1(850,745) v1(900,745)
  Bottom Layer w60: C20.1@3424.65,957.27 3424.65,1065.91 3490,1131.26 v1(3490,1180) v1(3490,1220)
+5V_U: C30.2 C33.1 C39.1 C107.2 C109.1 C110.1 C111.2 C113.2 D17.1 D35.1 Q7.2 R119.2 R121.2 R123.2 R125.2 U5.5 U7.1 U7.3 U20.5 U21.16 | length 6601.3
  Top Layer w25: U7.1@1743.3,2271.75 1743.3,2299.33 1763.96,2320 1805,2320 1818.1,2306.9 U7.3@1818.1,2271.75
  Top Layer w30: 1830,2265 1835,2260 1925.69,2260 1950,2284.31 1950,2302.93 ; v1@1950,2381.5 v1(1950,2386.1) ; 3990,2285 4035,2285 v1(4035,2150) v1(4035,2115) ; v1@4023.7,2141.3 v1@4032.4,2150 ; v1(4395,1970) v1(4435,1970) 4466.5,1938.5 R125.2@4466.5,1916.3 4466.5,1866.5 4447.4,1847.4 Q7.2@4427.24,1847.4
  Top Layer w35: U5.5@1817.68,2088.01 1835.28,2070.41 C30.2@1835.28,2012.14
  Top Layer w40: C39.1@1881.3,2381.5 v1@1950,2381.5 ; v1(1930,2025) v1(1890,2025) 1848.14,2025 C30.2@1835.28,2012.14 1982.14,2012.14 2015,2045 2015,2237.93 1950,2302.93 v1@1950,2381.5 ; v1@1981.5,2381.5 v1@1950,2381.5 ; R121.2@3678.5,2385 v1@3678.5,2428.5 ; C107.2@3981.5,2071.3 C109.1@3981.5,2141.3 v1@4023.7,2141.3 ; 3985,2290 R123.2@3985,2334.21 ; R123.2@3987.91,2341.3 R123.2@3995,2334.21 ; U21.16@4360,2430 4457.9,2429.63 C111.2@4526.38,2429.37 ; C111.2@4529.8,2432.8 v1@4612.2,2432.8 ; C110.1@4577.8,2275.29 4600,2297.49 4600,2420.59
  Top Layer w50: v1(4560,2210) 4580,2210 ; R119.2@4580,2150 4580,2210 ; 4580,2253.5 4580,2210 ; v1(4605,2210) 4580,2210
  Power w40: v1(1890,2025) v1(1930,2025) ; v1(1950,2386.1) v1(1985,2385) 1985,2460 2030,2505 2115,2505 2160.1,2459.9 3170.1,2459.9 3180,2450 3660,2450 v1(3680,2430) 3680,2415 3705,2390 3810,2390 3870,2450 3967.45,2450 3980,2437.45 ; v1(4035,2115) v1(4035,2150) 4035,2285 v1(4030,2290) 3980,2340 3980,2437.45 ; v1(4560,2210) 4585,2210 v1(4605,2210) ; v1(4575,2430) v1(4615,2430) 4607.55,2437.45 3980,2437.45
  Power w60: v1(4395,1970) v1(4435,1970) 4478.31,1970 4585,2076.69 4585,2210 v1@4585,2420
  Bottom Layer w20: D35.1@3986.22,2290 v1(4030,2290)
  Bottom Layer w30: v1(4035,2115) v1(4035,2150) v1@4035,2285
  Bottom Layer w50: C33.1@1946.83,2305.57 C33.1@1946.83,2320.57 1946.83,2361.83 1988.74,2403.74 ; 1965,2400 D17.1@1965,2436.26
  other v1: 4040,2255
+15V_Iso_L: C64.1 C66.1 C67.1 C72.1 C73.1 C138.1 Q1.2 Q4.3 Q14.2 R10.2 R13.2 R45.1 R47.2 R92.2 R152.2 TP6.1 U12.5 U15.5 | length 5687.3
  Top Layer w20: v1@1633.5,1241.5 1683.5,1241.5 TP6.1@1720,1205
  Top Layer w25: R45.1@2321.38,920 2321.38,936.38 2340,955 U12.5@2340,990.87 ; U15.5@2958.31,691.3 v1@2958.31,848.31 ; Q4.3@3848.98,1419.17 3898.98,1369.17 ; v1(3890,1410) 3898.98,1401.02 3898.98,1369.17 ; R92.2@3898.98,1336.58 3898.98,1369.17
  Top Layer w30: Q14.2@1309.69,1233.5 1316.22,1240.04 R152.2@1510,1240.04 ; C138.1@1583.54,1240.04 C138.1@1585,1241.5 ; Q1.2@2217.64,874.02 2249.02,874.02 2295,920 R45.1@2321.38,920 ; R47.2@2348.62,1160 v1(2390,1160) ; Q4.3@3848.98,1419.17 3875,1419.17 3884.17,1410 v1(3890,1410) v1(3930,1410) ; v1(4020,820) v1(4020,855)
  Top Layer w40: R152.2@1510,1240.04 C138.1@1583.54,1240.04 ; C138.1@1585,1241.5 v1@1633.5,1241.5 ; 4025,840 R13.2@4077.48,840
  Power w30: v1(4020,820) v1(4020,855)
  Power w40: v1(2337.01,957.01) 2362.01,957.01 ; v1(2390,1160) 2400.04,1149.96 2400.04,995.04 2400,965
  Power w50: v1(3890,1410) v1(3930,1410) 3975,1410 4030,1355 4030,1095 4045,1080 4045,880 v1(4020,855)
  Power w60: 2362.01,957.01 2877.99,957.01 ; v1@2960,777.45 v1(2960,810) v1(2960,850) 2960,875 2877.99,957.01 ; 4030,1095 3820,1095 3790,1065 3630.75,1065 3615.75,1080 3010,1080 2887.01,957.01 2877.99,957.01
  Bottom Layer w25: C64.1@2297.32,991.38 2297.32,977.68 2317.99,957.01 v1(2337.01,957.01) 2362.05,957.01 2390,984.96 v1(2390,1160)
  Bottom Layer w50: v1(1635,1240) 1635,1225 1790,1070 2140,1070 2230,1160 v1(2390,1160) ; R10.2@3640,1019.64 3735.36,1019.64 3835,920 3835,885 3882.5,837.5 4020,837.5
  other v1: 2960,770
+15V_Iso_U: C65.1 C69.1 C70.1 C76.1 C77.1 C137.1 Q2.2 Q8.2 R2.2 R15.2 R46.1 R49.2 R127.2 TP7.1 U13.5 U14.5 | length 4658.1
  Top Layer w25: v1(2512.18,2245) v1(2512.18,2286.09) v1(2512.18,2325) U14.5@2512.18,2433.43 ; U13.5@3264.13,2030 3321.38,2030 3326.38,2035 3341.38,2035 3341.38,2078.62 3300,2120 3268.62,2151.38 R46.1@3268.62,2170 3280,2181.38 3280,2279.65 Q2.2@3297.6,2297.24 ; R127.2@3852.52,1879.8 3925.55,1879.8 Q8.2@3932.76,1872.6
  Top Layer w30: v1(1945,2085) v1(1945,2125) ; v1(3010,2395) 3070,2395 TP7.1@3115,2440 ; TP7.1@3100,2440 TP7.1@3115,2440 ; TP7.1@3125,2440 TP7.1@3115,2440
  Top Layer w40: R2.2@1546.5,2495.5 1585.5,2495.5 v1(1595,2505) v1(1595,2465) ; v1(3280,2120) 3300,2120 v1(3320,2120) ; Q2.2@3297.6,2297.24 3297.6,2337.4 ; C137.1@3782.52,1879.8 R127.2@3852.52,1879.8
  Power w40: v1(1595,2465) v1(1595,2505)
  Power w50: v1(1595,2465) 1805,2465 1870,2400 1870,2135.9 1895.9,2110 1945,2110
  Power w60: 1940,2100 1945,2105 1945,2110 1950,2105 2400,2105 2512.18,2217.18 v1(2512.18,2245) v1(2512.18,2286.09) v1(2512.18,2325)
  Power w80: 3295,2135 3295,2320
  Ground w30: v1(3010,2395) 3010,2445
  Ground w60: v1(2512.18,2245) v1(2512.18,2286.09) v1(2512.18,2325) 2512.18,2352.18 2605,2445 3010,2445 3108.7,2445 3218.7,2335 v1(3280,2335) v1(3315,2335)
  Bottom Layer w30: C65.1@3238.62,2309.21 3264.21,2309.21 3280,2325 v1(3280,2335)
  Bottom Layer w40: R15.2@1880,2110 1930,2110 v1(1945,2125) v1(1945,2085) ; v1(3280,2120) 3285,2115 3712.89,2115 3775,2052.89 3775,1979.72 3859.72,1895 v1(3890,1895)
-8V_Iso_L: C72.2 C73.2 C74.2 C75.2 Q5.2 R19.2 TP8.1 U15.8 | length 2948.4
  Top Layer w20: TP8.1@2515,740 2535,760 2535,840 v1(2565,870) 2575,880 v1(2600,880)
  Top Layer w40: v1(3940,1220) v1(3940,1185) 3983.94,1185 R19.2@3988.94,1180
  Power w40: v1(2565,870) v1@2570,875 ; v1(2770,775) v1(2810,775) v1@2805,780 ; v1(2790,1275) 2790,1265 v1(2815,1240)
  Power w60: v1@2570,875 2695,875 2772.64,797.36 ; v1(2815,1240) 2882.52,1172.48 3347.48,1172.48 3475,1300 3885,1300 3940,1245 v1(3940,1220) v1(3940,1185)
  Bottom Layer w25: Q5.2@2772.4,1226.18 2791.18,1226.18 ; C73.2@2783.07,720 2782.91,719.84 2782.91,669.28 2794.87,657.32 C75.2@3000.3,657.32
  Bottom Layer w40: v1(2565,870) 2575,880 v1(2600,880) 2620,880 2825,1085 2825,1190 2810,1205 ; 2790,1227.36 v1(2790,1275) ; 2791.18,1226.18 2794.83,1222.08 2810,1205 ; v1@2810,1234.97 2810,1205 ; C75.2@3000.3,664 3000.3,709.45 C74.2@3008.17,717.32
  Bottom Layer w60: C73.2@2790,710 C72.2@2790,830
-8V_Iso_U: C76.2 C77.2 C78.2 C79.2 Q3.2 R8.2 TP9.1 U14.8 | length 3073.4
  Top Layer w35: R8.2@1626.5,2055 1626.5,2023.5 v1(1635,2015) 1635,1995 ; R8.2@1634.43,2052.07 1637.93,2052.07 v1(1675,2015) 1675,1995 ; v1(2110,1835) v1(2110,1875) ; 1635,1995 1675,1995 ; 1635,1995 v1(1635,1975) v1(1675,1975) 1675,1995
  Top Layer w50: 2815,2425 2820,2420 TP9.1@2875,2420
  Power w50: v1(2665,2385) v1(2765,2385) v1(2810,2385)
  Power w60: 1645,1995 1716.28,1995 1756.28,1955 1960,1955 2060,1855
  Power w80: 2060,1855 2095,1855
  Bottom Layer w25: 2090,1855 v1(2110,1835) v1(2110,1875) 2098.82,1863.82 Q3.2@2072.4,1863.82 2075,1866.42 2075,1885 2085,1895 2110,1895 ; C78.2@2447.72,2358.7 2455.59,2366.57 C79.2@2455.59,2418.7 ; C77.2@2711.93,2365 2711.93,2393.07
  Bottom Layer w40: C79.2@2474.29,2415 2715,2415 ; 2720,2410 2715,2415 ; 2730,2415 2715,2415
  Bottom Layer w50: v1(2110,1875) 2110,1895 2175.41,1960.41 2785.41,1960.41 2940,2115 2940,2370 2900,2410 2720,2410 ; C76.2@2699.57,2270 2711.93,2282.36 C77.2@2711.93,2345 C77.2@2711.93,2365
AIN_L: C98.1 D30.1 D38.2 Q13.3 R101.2 R158.2 U15.1 | length 4549.2
  Top Layer w30: R101.2@3403.5,680 3406.5,682.99 C98.1@3406.5,750 ; C98.1@3411.5,750 v1(3460,750)
  Top Layer w40: v1(980,1220) 950,1220 ; D38.2@1006.97,1155 965,1155 950,1170 950,1220 ; Q13.3@1106.5,1250 1115,1258.5 v1(1115,1290) ; R158.2@1223.5,1360 1223.5,1371.5 1195,1400 1000,1400 950,1350 950,1220 ; U15.1@3170,685.53 3382.97,685.53
  Bottom Layer w30: 1115,1255 1150,1255 1230,1175 1230,1125 1230,710 1260,680 2685,680 2720,715 2720,900 2815,995 3185,995 3230,950 3230,886.65 3255,861.65 3255,706.48 3275.94,685.53 D30.1@3308.98,685.53 3430.53,685.53 3460,715 v1(3460,750)
  Bottom Layer w40: v1(980,1220) 1015,1255 1115,1255 v1(1115,1290)
AIN_U: C87.1 D25.1 D32.2 Q7.3 R72.2 R135.2 U14.1 | length 3797.1
  Top Layer w30: 4265,1805 v1(4320,1750) 4340,1730 4371.1,1730 ; v1@4310,1790 4311.59,1788.44 4335.09,1765.36 4371.1,1730 ; 4332.76,1768.35 Q7.3@4332.76,1810 ; D32.2@4485,1998.35 4501.65,1998.35 4525,1975 4525,1780 4475,1730 4371.1,1730
  Top Layer w40: v1@2050,2460 2050,2435 2053.5,2431.5 U14.1@2310.25,2431.5 ; R135.2@4200,1838.5 4211.5,1838.5 4240,1810 Q7.3@4332.76,1810
  Bottom Layer w30: v1(2050,2425) 2050,2450 v1(2060,2460) 2061.15,2461.15 3018.85,2461.15 3060,2420 3060,2270 3090,2240 3285,2240 3363.7,2161.3 3827.2,2161.3 3963.5,2025 4045,2025 v1(4320,1750)
  other v1: 4300,1780
Analog_out_L: R116.2 TP26.1 U19.1 U19.4 | length 887.1
  Top Layer w25: v1(1955,160) 1975,160 2013.9,121.1 R116.2@2048.9,121.1 ; 2080.27,121.5 2080.27,123.51 2169.8,213.04 U19.4@2169.8,215.04
  Top Layer w35: R116.2@2035,121.5 2080.27,121.5 U19.1@2095,106.77
  Ground w20: v1(1955,160) 1966.08,160 1981.08,145 2515,145 TP26.1@2525,135
Analog_out_U: R114.2 TP25.1 U18.1 U18.4 | length 290.7
  Top Layer w25: TP25.1@3190,2996.72 3234.32,2952.4 U18.1@3246.97,2952.4 3288.54,2952.4 3301.1,2939.84 3301.1,2894.84 3318.34,2877.6 U18.4@3355.23,2877.6 R114.2@3405.04,2877.6
APWM_L: C97.1 J4.2 R99.1 | length 2149.6
  Top Layer w25: C97.1@3398.62,100 3410,111.38 R99.1@3410,158.5 ; v1@3576.5,158.5 3692.87,42.13 3811.38,42.13 4657.13,42.13 4750,135 4750,260 4860,370 5169.37,370 J4.2@5224.33,424.96
  Top Layer w30: R99.1@3410,158.5 v1@3453.5,158.5
  Bottom Layer w30: v1(3455,160) v1(3570,160)
APWM_U: C86.1 J3.2 R71.1 | length 2289.3
  Top Layer w20: J3.2@200,2580 200,2690 300,2790 635,2790 690,2845 975,2845 1045,2915 2010,2915 2064.03,2969.03 R71.1@2195,2969.03
  Top Layer w30: R71.1@2197.18,2966.85 2195,2969.03 2195,3018.62 C86.1@2206.38,3030
BUS_N: C50.2 R32.1 R42.1 TP5.1 | length 206.8
  Top Layer w15: TP5.1@455,105 520.31,105 C50.2@538.35,123.03 ; R32.1@482.01,181.3 486.93,176.38 R42.1@538.35,176.38 C50.2@538.35,123.03 ; C50.2@541.38,120 C50.2@538.35,123.03
BUS_P: C50.1 R37.1 R39.1 TP4.1 | length 190.7
  Top Layer w15: R37.1@561.5,40 564.98,40 588.62,63.64 ; R39.1@591.85,176.38 R39.1@588.35,176.38 588.35,120.28 588.62,120 588.62,93.62 588.62,63.64 ; TP4.1@625,55 588.62,63.64
BUSIN_N: C98.2 R31.1 R34.2 R41.2 | length 3662.1
  Top Layer w15: v1(450,1070) 440,1060 440,1020 R31.1@526.38,1020 527.68,1018.7 R34.2@527.68,931.5 ; R41.2@3253.62,745 3295,745 v1(3300,750) C98.2@3348.5,750
  Ground w15: v1(450,1070) 410,1070 390.36,1050.36 390.36,735 420.36,705 3275,705 3300,730 v1(3300,750)
BUSIN_P: R22.1 R28.2 R101.1 | length 4075.2
  Top Layer w15: v1(530,1180) 530,1200 542.91,1212.91 R22.1@600,1212.91 602.91,1210 680,1210 700,1190 R28.2@700,1150 ; R101.1@3466.5,680 3475,690 3486.5,715 v1(3507.96,715)
  Ground w15: 370,720 365.36,724.64 ; v1(530,1180) 430,1180 365.36,1114.64 365.36,724.64 ; v1(3507.96,715) 3502.96,720 3385,720 3345,680 410,680 365.36,724.64
CS_temp_L: J4.4 U10.4 | length 1821.4
  Top Layer w25: U10.4@3837.05,307.44 3837.05,130.83 3860,107.87 4629.89,107.87 4684.25,162.23 4684.25,290.74 4829.26,435.75 5099.26,435.75 5188.47,524.96 J4.4@5224.33,524.96
DU: MD1.14 R27.2 | length 1617.8
  Top Layer w20: R27.2@615.83,1570 615.83,1635.83 680,1700 1735,1700 1965,1470 MD1.14@2045.91,1470
EN_L: R16.1 R20.2 U6.4 | length 424.1
  Top Layer w25: v1(4935,1260) R16.1@4935,1305.75 ; v1@4966.3,1019.84 4966.3,1042
  Top Layer w40: R16.1@4946.1,1316.85 R20.2@5024.61,1316.85
  Bottom Layer w25: v1(4935,1260) 4935,1043.78 4962.64,1016.14 4985,1016.14
  other v1: 4970,1016.14
EN_U: R5.1 R9.2 U2.4 | length 410.6
  Top Layer w30: 658.82,2303.82 658.82,2320.29 v1(665,2326.47)
  Top Layer w40: 622.61,2022.61 640,2040 v1(640,2105)
  Top Layer w50: R9.2@598.59,2022.61 R5.1@662.61,2022.61
  Bottom Layer w40: v1(640,2105) 665,2130 v1(665,2326.47)
FB_L: R17.1 U6.2 | length 60.5
  Top Layer w20: R17.1@4910.13,1125.35 4922.88,1112.59 U6.2@4965.32,1112.59
FB_U: R6.1 U2.2 | length 53.7
  Top Layer w15: U2.2@661.9,2230.01 713.52,2230.01 R6.1@715,2231.5
FLT_L: C95.1 D28.1 J2.9 R86.1 U15.13 | length 4263
  Top Layer w25: C95.1@2976.06,143.62 R86.1@3027.38,143.62 3027.38,160.62 3008.31,179.69 ; 3008.31,145.05 3008.31,179.69 ; U15.13@3008.31,307.44 3008.31,179.69
  Top Layer w35: R86.1@3027.38,143.62 v1@3063.62,143.62 ; v1(4870,145) D28.1@4913.5,145
  Power w15: J2.9@5246.77,1214.96 5296.77,1264.96 5404.96,1264.96
  Power w20: v1(4870,145) 5170,145 5190,165 5190,214.42 5288.45,312.87 5433.45,312.87 5452.13,331.55 5452.13,1245 5432.17,1264.96 5404.96,1264.96
  Ground w20: v1(3065,145) 3065,208.82 3163.63,307.45 4841.37,307.45 4888.82,260 4890,260 4905,245 4905,172.44 4877.56,145 v1(4870,145)
FLT_U: C84.1 D23.1 J3.10 R60.1 U14.13 | length 4092.1
  Top Layer w25: J3.10@200,2180 137.45,2180 87.45,2230 87.45,2762.45 150,2825 225,2825 320,2920 D23.1@478.5,2920 ; R60.1@2435,2921.38 2435,2895 2462.18,2867.82 U14.13@2462.18,2817.28 ; v1@2713.31,2986.69 C84.1@2713.31,3031.1
  Top Layer w35: 410,2935 v1(410,2955)
  Power w25: v1(410,2955) 452.55,2912.45 1767.55,2912.45 1820,2860 2232.5,2860 2302.5,2930 2435,2930 2460,2905 v1(2460,2875)
  Bottom Layer w20: v1@2462.45,2872.55 v1(2460,2875) 2800,2875 2840,2915 2840,2985 2806.78,3018.22 2732.71,3018.22 2715,3000.51 v1(2715,2985)
Gate_L: C91.1 D26.2 MD1.8 R89.2 R91.2 R93.2 R94.2 R95.2 R96.2 R98.2 R105.2 R148.2 TP20.1 | length 1280.7
  Top Layer w20: R148.2@1930,1055 1965,1090 2105,1090 2214.6,1199.6 2545,1199.6 ; R93.2@2705,1180 TP20.1@2705,1260
  Top Layer w120: 2904.17,1210.32 MD1.8@2904.17,1470
  Bottom Layer w40: MD1.8@2904.17,1434.33 MD1.8@2904.17,1470
  Bottom Layer w80: MD1.8@2902.99,1468.82 MD1.8@2904.17,1470
  Bottom Layer w100: D26.2@2902.99,1240 MD1.8@2902.99,1468.82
